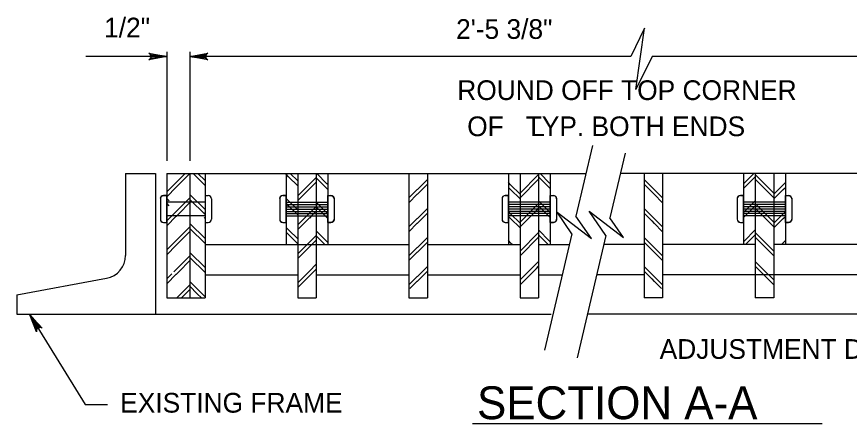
# Model space of a CAD drawing. Extents: x -0.3 to 6.9, y -6.5 to 3.5.
# Drawn here: x -0.154 to 2.383, y -2.494 to -1.256 of the extents above; entities that cross this region are included whole.
import ezdxf

# ---------------------------------------------------------------- set-up
doc = ezdxf.new("R2010")
doc.units = 0
for name, color, linetype in [('DETL-DIMS', 7, 'Continuous'), ('DETL-LINE', 7, 'Continuous'), ('DETL-NOTE', 7, 'Continuous'), ('DETL-PATT', 7, 'Continuous'), ('DETL-TITL', 7, 'Continuous')]:
    doc.layers.add(name, color=color, linetype=linetype)

msp = doc.modelspace()

# ---------------------------------------------------------------- linework, layer by layer
at = {"layer": 'DETL-DIMS'}
for p, q in [((0.3034, -1.3634), (0.3034, -1.695)), ((0.374, -1.3634), (0.374, -1.695)), ((0.3034, -1.3777), (0.0567, -1.3777)), ((1.7176, -1.3777), (0.374, -1.3777)), ((3.1968, -1.3777), (1.7824, -1.3777)), ((-0.1135, -2.1637), (0.0544, -2.4375)), ((0.0544, -2.4375), (0.1231, -2.4375))]:
    msp.add_line(p, q, dxfattribs=at)
for points in [[(1.7824, -1.3777), (1.7332, -1.4781), (1.7586, -1.2915), (1.7176, -1.3777)], [(0.3034, -1.3777), (0.2486, -1.388), (0.2528, -1.385), (0.255, -1.3814), (0.2557, -1.3777), (0.255, -1.374), (0.2528, -1.3703), (0.2486, -1.3674), (0.3034, -1.3777), (0.2528, -1.3703), (0.255, -1.374), (0.3034, -1.3777), (0.2557, -1.3777), (0.255, -1.3814), (0.3034, -1.3777), (0.2528, -1.385)], [(0.374, -1.3777), (0.4289, -1.3674), (0.4246, -1.3703), (0.4225, -1.374), (0.4218, -1.3777), (0.4225, -1.3814), (0.4246, -1.385), (0.4289, -1.388), (0.374, -1.3777), (0.4246, -1.385), (0.4225, -1.3814), (0.374, -1.3777), (0.4218, -1.3777), (0.4225, -1.374), (0.374, -1.3777), (0.4246, -1.3703)], [(0.374, -1.3777), (0.4289, -1.3674), (0.4246, -1.3703), (0.4225, -1.374), (0.4218, -1.3777), (0.4225, -1.3814), (0.4246, -1.385), (0.4289, -1.388), (0.374, -1.3777), (0.4246, -1.385), (0.4225, -1.3814), (0.374, -1.3777), (0.4218, -1.3777), (0.4225, -1.374), (0.374, -1.3777), (0.4246, -1.3703)], [(-0.1135, -2.1637), (-0.0761, -2.205), (-0.0808, -2.203), (-0.0851, -2.203), (-0.0885, -2.2044), (-0.0913, -2.2069), (-0.0933, -2.2107), (-0.0936, -2.2158), (-0.1135, -2.1637), (-0.0933, -2.2107), (-0.0913, -2.2069), (-0.1135, -2.1637), (-0.0885, -2.2044), (-0.0851, -2.203), (-0.1135, -2.1637), (-0.0808, -2.203)]]:
    msp.add_lwpolyline(points, dxfattribs=at)
at = {"layer": 'DETL-LINE'}
for p, q in [((1.6008, -1.6488), (1.5502, -1.8639)), ((1.6999, -1.6721), (1.6537, -1.8688)), ((0.1777, -1.7339), (0.1777, -1.9832)), ((0.1777, -1.7339), (0.2695, -1.7339)), ((0.2695, -1.7339), (0.2695, -2.1619)), ((0.3034, -1.7339), (0.3034, -2.1127)), ((0.3034, -1.7339), (1.5808, -1.7339)), ((0.4199, -1.7339), (0.4199, -2.1127)), ((0.667, -1.7339), (0.667, -1.9501)), ((0.7023, -1.7339), (0.7023, -2.1127)), ((0.7587, -1.7339), (0.7587, -2.1127)), ((0.794, -1.7339), (0.794, -1.9501)), ((1.0411, -1.7339), (1.0411, -2.1127)), ((1.0411, -1.7345), (1.0417, -1.7339)), ((1.0976, -1.7339), (1.0976, -2.1127)), ((1.3446, -1.7339), (1.3446, -1.9501)), ((1.3799, -1.7339), (1.3799, -2.1127)), ((1.4364, -1.7339), (1.4364, -2.1127)), ((1.4717, -1.7339), (1.4717, -1.9501)), ((3.1968, -1.7339), (1.6854, -1.7339)), ((1.7577, -1.7339), (1.7577, -2.1127)), ((1.8142, -1.7339), (1.8142, -2.1127)), ((2.0612, -1.7339), (2.0612, -1.9501)), ((2.0965, -1.7339), (2.0965, -2.1127)), ((2.153, -1.7339), (2.153, -2.1127)), ((2.1883, -1.7339), (2.1883, -1.9501)), ((0.2936, -1.8012), (0.3034, -1.8012)), ((0.4199, -1.8012), (0.4297, -1.8012)), ((0.6572, -1.8012), (0.667, -1.8012)), ((0.794, -1.8012), (0.8038, -1.8012)), ((1.3348, -1.8012), (1.3446, -1.8012)), ((1.4717, -1.8012), (1.4815, -1.8012)), ((2.0514, -1.8012), (2.0612, -1.8012)), ((2.1883, -1.8012), (2.1981, -1.8012)), ((0.2838, -1.811), (0.2838, -1.873)), ((0.311, -1.8172), (0.3034, -1.8096)), ((0.4199, -1.8208), (0.3034, -1.8208)), ((0.311, -1.8319), (0.3034, -1.8243)), ((0.4395, -1.811), (0.4395, -1.873)), ((0.6474, -1.811), (0.6474, -1.873)), ((0.667, -1.8208), (0.794, -1.8208)), ((0.8136, -1.811), (0.8136, -1.873)), ((1.325, -1.811), (1.325, -1.873)), ((1.4717, -1.8208), (1.3446, -1.8208)), ((1.4913, -1.811), (1.4913, -1.873)), ((2.1883, -1.8208), (2.0612, -1.8208)), ((2.2079, -1.811), (2.2079, -1.873)), ((0.667, -1.8279), (0.794, -1.8279)), ((0.667, -1.8349), (0.794, -1.8349)), ((0.667, -1.842), (0.794, -1.842)), ((0.667, -1.8491), (0.794, -1.8491)), ((0.7457, -1.8617), (0.7587, -1.8487)), ((1.4717, -1.8279), (1.3446, -1.8279)), ((1.4717, -1.8349), (1.3446, -1.8349)), ((1.4717, -1.842), (1.3446, -1.842)), ((1.4717, -1.8491), (1.3446, -1.8491)), ((2.1883, -1.8279), (2.0612, -1.8279)), ((2.1883, -1.8349), (2.0612, -1.8349)), ((2.1883, -1.842), (2.0612, -1.842)), ((2.1883, -1.8491), (2.0612, -1.8491)), ((0.4199, -1.8632), (0.3034, -1.8632)), ((0.4171, -1.8532), (0.4199, -1.856)), ((0.667, -1.8561), (0.794, -1.8561)), ((0.667, -1.8632), (0.794, -1.8632)), ((1.4717, -1.8561), (1.3446, -1.8561)), ((1.4717, -1.8632), (1.3446, -1.8632)), ((2.1883, -1.8561), (2.0612, -1.8561)), ((2.1883, -1.8632), (2.0612, -1.8632)), ((0.2936, -1.8828), (0.3034, -1.8828)), ((0.4199, -1.8828), (0.4297, -1.8828)), ((0.6572, -1.8828), (0.667, -1.8828)), ((0.794, -1.8828), (0.8038, -1.8828)), ((1.3348, -1.8828), (1.3446, -1.8828)), ((1.4717, -1.8828), (1.4815, -1.8828)), ((2.0514, -1.8828), (2.0612, -1.8828)), ((2.1883, -1.8828), (2.1981, -1.8828)), ((1.5376, -1.9178), (1.4544, -2.2714)), ((1.641, -1.9227), (1.5535, -2.2947)), ((0.4199, -1.9501), (1.0411, -1.9501)), ((1.0976, -1.9501), (1.3799, -1.9501)), ((1.4364, -1.9501), (1.53, -1.9501)), ((1.7577, -1.9501), (1.6345, -1.9501)), ((2.0965, -1.9501), (1.8142, -1.9501)), ((2.4354, -1.9501), (2.153, -1.9501)), ((-0.1531, -2.103), (0.12, -2.0526)), ((0.4199, -2.0419), (0.7023, -2.0419)), ((0.7587, -2.0419), (1.0411, -2.0419)), ((1.0976, -2.0419), (1.3799, -2.0419)), ((1.4364, -2.0419), (1.5084, -2.0419)), ((1.7577, -2.0419), (1.613, -2.0419)), ((2.4354, -2.0419), (1.8142, -2.0419)), ((-0.154, -2.1032), (-0.154, -2.1619)), ((0.3034, -2.1127), (0.4199, -2.1127)), ((0.7023, -2.1127), (0.7587, -2.1127)), ((1.0411, -2.1127), (1.0976, -2.1127)), ((1.3799, -2.1127), (1.4364, -2.1127)), ((1.8142, -2.1127), (1.7577, -2.1127)), ((2.153, -2.1127), (2.0965, -2.1127)), ((-0.154, -2.1619), (1.4747, -2.1619)), ((2.9598, -2.1619), (1.5847, -2.1619))]:
    msp.add_line(p, q, dxfattribs=at)
for points in [[(0.3034, -1.8012), (0.2936, -1.8012), (0.2891, -1.8027), (0.287, -1.8041), (0.2854, -1.8061), (0.2837, -1.8088), (0.2838, -1.811), (0.2838, -1.873), (0.2847, -1.8775), (0.2864, -1.8795), (0.2887, -1.8815), (0.2936, -1.8828), (0.3034, -1.8828)], [(0.667, -1.8012), (0.6572, -1.8012), (0.6533, -1.8019), (0.6519, -1.8026), (0.6498, -1.8044), (0.6484, -1.8061), (0.6473, -1.8083), (0.6474, -1.811), (0.6474, -1.873), (0.648, -1.8767), (0.6494, -1.8785), (0.6512, -1.8803), (0.653, -1.8813), (0.6547, -1.882), (0.6572, -1.8828), (0.667, -1.8828)], [(0.794, -1.8012), (0.8038, -1.8012), (0.8078, -1.8019), (0.8103, -1.8037), (0.8121, -1.8065), (0.8135, -1.809), (0.8136, -1.811), (0.8136, -1.873), (0.8131, -1.876), (0.8124, -1.8778), (0.811, -1.8796), (0.8093, -1.881), (0.8038, -1.8828), (0.794, -1.8828)], [(1.3446, -1.8012), (1.3348, -1.8012), (1.331, -1.8019), (1.3295, -1.8026), (1.3274, -1.8044), (1.326, -1.8061), (1.325, -1.8083), (1.325, -1.811), (1.325, -1.873), (1.3257, -1.8767), (1.3271, -1.8785), (1.3288, -1.8803), (1.3306, -1.8813), (1.3324, -1.882), (1.3348, -1.8828), (1.3446, -1.8828)], [(1.4717, -1.8012), (1.4815, -1.8012), (1.4855, -1.8019), (1.488, -1.8037), (1.4897, -1.8065), (1.4911, -1.809), (1.4913, -1.811), (1.4913, -1.873), (1.4908, -1.876), (1.4901, -1.8778), (1.4887, -1.8796), (1.4869, -1.881), (1.4815, -1.8828), (1.4717, -1.8828)], [(2.0612, -1.8012), (2.0514, -1.8012), (2.0476, -1.8019), (2.0462, -1.8026), (2.044, -1.8044), (2.0426, -1.8061), (2.0416, -1.8083), (2.0416, -1.811), (2.0416, -1.873), (2.0423, -1.8767), (2.0437, -1.8785), (2.0455, -1.8803), (2.0472, -1.8813), (2.049, -1.882), (2.0514, -1.8828), (2.0612, -1.8828)], [(2.1883, -1.8012), (2.1981, -1.8012), (2.2021, -1.8019), (2.2046, -1.8037), (2.2063, -1.8065), (2.2077, -1.809), (2.2079, -1.811), (2.2079, -1.873), (2.2074, -1.876), (2.2067, -1.8778), (2.2053, -1.8796), (2.2035, -1.881), (2.1981, -1.8828), (2.1883, -1.8828)]]:
    msp.add_lwpolyline(points, close=True, dxfattribs=at)
for points in [[(1.5376, -1.9178), (1.4929, -1.8513), (1.5971, -1.932), (1.5502, -1.8639)], [(1.641, -1.9227), (1.5908, -1.8481), (1.695, -1.9288), (1.6537, -1.8688)]]:
    msp.add_lwpolyline(points, dxfattribs=at)
for centre, radius, start, end in [((0.2936, -1.811), 0.0098, 90, 180), ((0.4297, -1.811), 0.0098, 0, 90), ((0.6572, -1.811), 0.0098, 90, 180), ((0.8038, -1.811), 0.0098, 0, 90), ((1.3348, -1.811), 0.0098, 90, 180), ((1.4815, -1.811), 0.0098, 0, 90), ((2.0514, -1.811), 0.0098, 90, 180), ((2.1981, -1.811), 0.0098, 0, 90), ((0.2936, -1.873), 0.0098, 180, 270), ((0.4297, -1.873), 0.0098, 270, 0), ((0.6572, -1.873), 0.0098, 180, 270), ((0.8038, -1.873), 0.0098, 270, 0), ((1.3348, -1.873), 0.0098, 180, 270), ((1.4815, -1.873), 0.0098, 270, 0), ((2.0514, -1.873), 0.0098, 180, 270), ((2.1981, -1.873), 0.0098, 270, 0), ((0.1071, -1.9832), 0.0706, 280.4675, 0)]:
    msp.add_arc(centre, radius, start, end, dxfattribs=at)
at = {"layer": 'DETL-PATT'}
for p, q in [((0.3325, -1.7611), (0.3598, -1.7339)), ((0.374, -1.7343), (0.3325, -1.7758)), ((0.374, -1.7339), (0.374, -2.1127)), ((0.4199, -1.7703), (0.3835, -1.7339)), ((0.4199, -1.7556), (0.3982, -1.7339)), ((0.6745, -1.7437), (0.667, -1.7361)), ((0.7023, -1.7714), (0.6745, -1.7437)), ((0.7023, -1.7567), (0.6795, -1.7339)), ((0.7383, -1.7662), (0.7587, -1.7457)), ((0.7912, -1.7797), (0.7587, -1.7472)), ((0.7912, -1.765), (0.7602, -1.7339)), ((1.3799, -1.7934), (1.4364, -1.7369)), ((1.4699, -1.7776), (1.4364, -1.7441)), ((1.4699, -1.7629), (1.4409, -1.7339)), ((1.8142, -1.7345), (1.8135, -1.7339)), ((2.063, -1.7629), (2.092, -1.7339)), ((2.063, -1.7776), (2.0965, -1.7441)), ((2.153, -1.7934), (2.0965, -1.7369)), ((0.3034, -1.7899), (0.3322, -1.7611)), ((0.3034, -1.8046), (0.3322, -1.7758)), ((0.7023, -1.8019), (0.738, -1.7662)), ((0.7587, -1.7604), (0.7383, -1.7809)), ((0.794, -1.7678), (0.7912, -1.765)), ((1.0669, -1.7825), (1.0976, -1.7519)), ((1.0976, -1.7666), (1.0669, -1.7972)), ((1.3512, -1.768), (1.3446, -1.7615)), ((1.3799, -1.7968), (1.3512, -1.768)), ((1.3799, -1.8081), (1.4364, -1.7516)), ((1.4717, -1.7647), (1.4699, -1.7629)), ((1.7884, -1.7825), (1.7577, -1.7519)), ((1.7577, -1.7666), (1.7884, -1.7972)), ((2.0612, -1.7647), (2.063, -1.7629)), ((2.153, -1.8081), (2.0965, -1.7516)), ((2.153, -1.7968), (2.1817, -1.768)), ((2.1817, -1.768), (2.1883, -1.7615)), ((0.4199, -1.8439), (0.374, -1.798)), ((0.7023, -1.8166), (0.738, -1.7809)), ((0.794, -1.7825), (0.7912, -1.7797)), ((1.0411, -1.808), (1.0666, -1.7825)), ((1.0411, -1.8227), (1.0666, -1.7972)), ((1.3512, -1.7827), (1.3446, -1.7762)), ((1.3799, -1.8115), (1.3512, -1.7827)), ((1.4717, -1.7794), (1.4699, -1.7776)), ((1.8142, -1.808), (1.7887, -1.7825)), ((1.8142, -1.8227), (1.7887, -1.7972)), ((2.0612, -1.7794), (2.063, -1.7776)), ((2.153, -1.8115), (2.1817, -1.7827)), ((2.1817, -1.7827), (2.1883, -1.7762)), ((0.3325, -1.8494), (0.374, -1.8079)), ((0.3399, -1.8567), (0.374, -1.8226)), ((0.4199, -1.8586), (0.374, -1.8127)), ((0.6745, -1.8172), (0.667, -1.8096)), ((0.6745, -1.8319), (0.667, -1.8243)), ((0.7023, -1.8449), (0.6745, -1.8172)), ((0.7912, -1.8532), (0.7587, -1.8207)), ((1.4152, -1.8464), (1.4364, -1.8252)), ((1.4699, -1.8511), (1.4364, -1.8176)), ((2.0416, -1.811), (2.0416, -1.873)), ((2.063, -1.8511), (2.0965, -1.8176)), ((2.1177, -1.8464), (2.0965, -1.8252)), ((0.3249, -1.8567), (0.3322, -1.8494)), ((0.7023, -1.8596), (0.6745, -1.8319)), ((0.7383, -1.8544), (0.7587, -1.834)), ((0.7912, -1.8679), (0.7587, -1.8354)), ((1.0669, -1.8708), (1.0976, -1.8401)), ((1.3512, -1.8563), (1.3446, -1.8497)), ((1.3799, -1.8816), (1.4152, -1.8464)), ((1.3799, -1.8963), (1.4299, -1.8464)), ((1.4299, -1.8464), (1.4364, -1.8399)), ((1.4699, -1.8658), (1.4364, -1.8323)), ((1.4699, -1.8511), (1.4717, -1.8529)), ((1.7884, -1.8708), (1.7577, -1.8401)), ((2.063, -1.8511), (2.0612, -1.8529)), ((2.063, -1.8658), (2.0965, -1.8323)), ((2.103, -1.8464), (2.0965, -1.8399)), ((2.153, -1.8963), (2.103, -1.8464)), ((2.153, -1.8816), (2.1177, -1.8464)), ((2.1817, -1.8563), (2.1883, -1.8497)), ((0.3034, -1.8781), (0.3249, -1.8567)), ((0.3034, -1.8928), (0.3322, -1.8641)), ((0.3399, -1.8567), (0.3322, -1.8644)), ((0.4199, -1.8707), (0.4171, -1.8679)), ((0.7023, -1.8901), (0.7307, -1.8617)), ((0.7023, -1.9048), (0.738, -1.8691)), ((0.7307, -1.8617), (0.738, -1.8544)), ((0.7457, -1.8617), (0.738, -1.8694)), ((0.7912, -1.8532), (0.794, -1.856)), ((0.794, -1.8707), (0.7912, -1.8679)), ((1.0592, -1.8781), (1.0666, -1.8708)), ((1.0743, -1.8781), (1.0976, -1.8548)), ((1.3512, -1.871), (1.3446, -1.8644)), ((1.3512, -1.8563), (1.3799, -1.885)), ((1.3799, -1.8997), (1.3512, -1.871)), ((1.4717, -1.8676), (1.4699, -1.8658)), ((1.781, -1.8781), (1.7577, -1.8548)), ((1.796, -1.8781), (1.7887, -1.8708)), ((2.0612, -1.8676), (2.063, -1.8658)), ((2.1817, -1.8563), (2.153, -1.885)), ((2.153, -1.8997), (2.1817, -1.871)), ((2.1817, -1.871), (2.1883, -1.8644)), ((0.3325, -1.9376), (0.374, -1.8961)), ((0.4199, -1.9321), (0.374, -1.8862)), ((0.4199, -1.9468), (0.374, -1.9009)), ((0.6745, -1.9054), (0.667, -1.8979)), ((1.0411, -1.8963), (1.0592, -1.8781)), ((1.0411, -1.911), (1.0666, -1.8855)), ((1.0743, -1.8781), (1.0666, -1.8858)), ((1.781, -1.8781), (1.7887, -1.8858)), ((1.8142, -1.911), (1.7887, -1.8855)), ((1.8142, -1.8963), (1.796, -1.8781)), ((0.374, -1.9108), (0.3325, -1.9523)), ((0.6745, -1.9201), (0.667, -1.9126)), ((0.6745, -1.9054), (0.7023, -1.9332)), ((0.7023, -1.9479), (0.6745, -1.9201)), ((0.7383, -1.9426), (0.7587, -1.9222)), ((0.7912, -1.9414), (0.7587, -1.9089)), ((0.7839, -1.9488), (0.7587, -1.9236)), ((1.0669, -1.959), (1.0976, -1.9284)), ((1.3799, -1.9699), (1.4364, -1.9134)), ((1.3799, -1.9846), (1.4364, -1.9281)), ((1.4699, -1.9394), (1.4364, -1.9059)), ((1.4626, -1.9467), (1.4364, -1.9206)), ((1.7884, -1.959), (1.7577, -1.9284)), ((2.063, -1.9394), (2.0965, -1.9059)), ((2.0704, -1.9467), (2.0965, -1.9206)), ((2.153, -1.9699), (2.0965, -1.9134)), ((2.153, -1.9846), (2.0965, -1.9281)), ((0.3034, -1.9664), (0.3322, -1.9376)), ((0.3034, -1.9811), (0.3322, -1.9523)), ((0.7023, -1.9784), (0.738, -1.9426)), ((0.7587, -1.9369), (0.7383, -1.9573)), ((0.7849, -1.9501), (0.7839, -1.9491)), ((0.7912, -1.9414), (0.794, -1.9442)), ((1.0976, -1.9431), (1.0669, -1.9737)), ((1.3512, -1.9445), (1.3446, -1.938)), ((1.3512, -1.9445), (1.3568, -1.9501)), ((1.4656, -1.9501), (1.4626, -1.9471)), ((1.4699, -1.9394), (1.4717, -1.9412)), ((1.7577, -1.9431), (1.7884, -1.9737)), ((2.063, -1.9394), (2.0612, -1.9412)), ((2.0673, -1.9501), (2.0704, -1.9471)), ((2.1817, -1.9445), (2.1761, -1.9501)), ((2.1817, -1.9445), (2.1883, -1.938)), ((0.4199, -2.0203), (0.374, -1.9744)), ((0.7023, -1.9931), (0.738, -1.9573)), ((1.0411, -1.9845), (1.0666, -1.959)), ((1.0411, -1.9992), (1.0666, -1.9737)), ((1.8142, -1.9845), (1.7887, -1.959)), ((1.8142, -1.9992), (1.7887, -1.9737)), ((0.3325, -2.0258), (0.374, -1.9843)), ((0.3399, -2.0332), (0.374, -1.999)), ((0.4199, -2.035), (0.374, -1.9892)), ((1.4152, -2.0229), (1.4364, -2.0016)), ((2.1177, -2.0229), (2.0965, -2.0016)), ((0.3249, -2.0332), (0.3322, -2.0258)), ((0.7383, -2.0309), (0.7587, -2.0104)), ((0.7457, -2.0382), (0.7587, -2.0252)), ((1.0669, -2.0472), (1.0976, -2.0166)), ((1.3799, -2.0581), (1.4152, -2.0229)), ((1.3799, -2.0728), (1.4299, -2.0229)), ((1.4299, -2.0229), (1.4364, -2.0163)), ((1.7884, -2.0472), (1.7577, -2.0166)), ((2.103, -2.0229), (2.0965, -2.0163)), ((2.153, -2.0728), (2.103, -2.0229)), ((2.153, -2.0581), (2.1177, -2.0229)), ((0.3034, -2.0546), (0.3187, -2.0393)), ((0.3034, -2.0693), (0.3322, -2.0405)), ((0.3399, -2.0332), (0.3322, -2.0409)), ((0.7023, -2.0666), (0.7307, -2.0382)), ((0.7023, -2.0813), (0.738, -2.0456)), ((0.7307, -2.0382), (0.738, -2.0309)), ((0.7457, -2.0382), (0.738, -2.0459)), ((1.0411, -2.0727), (1.0592, -2.0546)), ((1.0592, -2.0546), (1.0666, -2.0472)), ((1.0743, -2.0546), (1.0666, -2.0623)), ((1.0743, -2.0546), (1.0976, -2.0313)), ((1.781, -2.0546), (1.7577, -2.0313)), ((1.781, -2.0546), (1.7887, -2.0623)), ((1.796, -2.0546), (1.7887, -2.0472)), ((1.8142, -2.0727), (1.796, -2.0546)), ((0.3339, -2.1127), (0.374, -2.0726)), ((0.374, -2.0627), (0.4112, -2.0998)), ((0.3965, -2.0998), (0.374, -2.0774)), ((1.0441, -2.0845), (1.0666, -2.062)), ((1.8112, -2.0845), (1.7887, -2.062)), ((0.374, -2.0873), (0.3486, -2.1127)), ((0.409, -2.1127), (0.3965, -2.1002)), ((0.4199, -2.1089), (0.4112, -2.1002))]:
    msp.add_line(p, q, dxfattribs=at)
at = {"layer": 'DETL-TITL'}
msp.add_line((1.2355, -2.4945), (2.3008, -2.4945), dxfattribs=at)

# ---------------------------------------------------------------- texts
at = {"layer": 'DETL-NOTE'}
for s, p in [('1/2"', (0.1125, -1.3196)), ('2\'-5 3/8"', (1.185, -1.3241)), ('ROUND OFF TOP CORNER', (1.1886, -1.5102)), ('OF   TYP. BOTH ENDS', (1.2188, -1.6202)), ('L', (1.4106, -1.6202)), ('ADJUSTMENT DEVICE', (1.8053, -2.2982)), ('EXISTING FRAME', (0.1615, -2.4619))]:
    msp.add_text(s, height=0.06, dxfattribs=at).set_placement(p)
at = {"layer": 'DETL-TITL'}
msp.add_text('SECTION A-A', height=0.1, dxfattribs=at).set_placement((1.2488, -2.4819))

doc.saveas('drawing.dxf')
